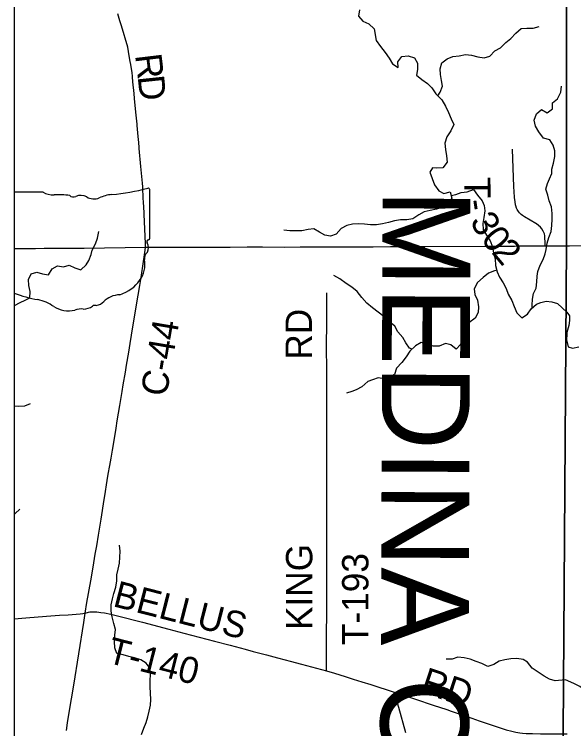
# Model space of a CAD drawing. Extents: x 0 to 34, y 0 to 22.
# Drawn here: x 2.1 to 3.306, y 17.388 to 18.93 of the extents above; entities that cross this region are included whole.
import ezdxf

# ---------------------------------------------------------------- set-up
doc = ezdxf.new("R2010")
doc.units = 0
for name, color, linetype in [('Default', 7, 'Continuous'), ('GM_X_County_Road', 7, 'Continuous'), ('GM_X_County_Road_Text', 7, 'Continuous'), ('GM_X_County_Text', 7, 'Continuous'), ('GM_X_Minor_River', 7, 'Continuous'), ('GM_X_State_Location', 7, 'Continuous'), ('GM_X_State_Route', 7, 'Continuous'), ('GM_X_Township_Road', 7, 'Continuous'), ('GM_X_Township_Road_Text', 7, 'Continuous'), ('SH_Cut_Line', 7, 'Continuous'), ('SH_Data', 7, 'Continuous')]:
    doc.layers.add(name, color=color, linetype=linetype)

msp = doc.modelspace()

# ---------------------------------------------------------------- linework, layer by layer
at = {"layer": 'Default'}
msp.add_lwpolyline([(3.2826, 20.9), (2.1, 20.9), (2.1, 15.8248), (3.2829, 15.8433), (3.2832, 16.3898), (3.2835, 17.0107), (3.2837, 17.3796), (3.2907, 18.4315), (3.2904, 19.1173), (3.2901, 19.68), (3.2888, 19.8918), (3.2845, 20.5998), (3.2843, 20.6124)], close=True, dxfattribs=at)
for points in [[(8.1749, 20.9), (3.2826, 20.9), (3.2843, 20.6124), (3.2845, 20.5998), (3.2888, 19.8918), (3.2901, 19.68), (3.2904, 19.1173), (3.2907, 18.4315), (3.2837, 17.3796), (3.2835, 17.0107), (3.2832, 16.3898), (3.2829, 15.8433), (3.425, 15.8449), (3.4609, 15.8448), (3.6703, 15.8472), (4.3446, 15.8524), (4.6273, 15.8569)], [(2.1621, 18.5464), (2.1, 18.5464), (2.1, 18.3281)], [(2.3919, 18.4467), (2.3919, 18.4467), (2.3919, 18.4467), (2.3919, 18.5516)]]:
    msp.add_lwpolyline(points, dxfattribs=at)
for centre, major_axis, start_param, end_param in [((2.1851, 18.5696), (0.037, 0), 4.042888, 4.731792), ((2.2745, 18.8193), (0.3495, 0), 4.814394, 5.042369), ((2.3883, 18.5518), (0.00367, 0), 6.197627, 7.989034), ((2.1974, 18.4341), (0.133, 0), 1.404758, 1.657859), ((2.2276, 18.5444), (0.0107, 0), 3.836095, 5.185415), ((2.2432, 18.5213), (0.0222, 0), 0.950623, 2.079405), ((2.2719, 18.553), (0.0267, 0), 4.08156, 5.145723), ((2.3191, 18.4853), (0.0703, 0), 1.699012, 2.107814), ((2.3911, 18.439), (0.00568, 0), 1.883978, 3.671073), ((2.355, 18.4258), (0.0341, 0), 5.934695, 6.695948), ((2.388, 18.4463), (0.00393, 0), 5.05454, 6.418171), ((2.4051, 18.4029), (0.0248, 0), 2.387724, 3.262537), ((2.2941, 18.3896), (0.0874, 0), 5.101753, 6.440018), ((2.2066, 18.5111), (0.2524, 0), 4.276441, 4.488961), ((2.1313, 18.2529), (0.079, 0), 0.823519, 1.323587), ((2.331, 18.2867), (0.0479, 0), 1.647645, 2.488434), ((2.2167, 18.3303), (0.0501, 0), 4.026481, 4.996735), ((2.2494, 18.3153), (0.0267, 0), 4.691044, 5.507374), ((2.2735, 18.2959), (0.00752, 0), 1.147584, 2.315152), ((2.2703, 18.3235), (0.0282, 0), 4.937069, 5.64225), ((2.2457, 18.2611), (0.0412, 0), 1.495662, 1.94098)]:
    msp.add_ellipse(centre, major_axis=major_axis, ratio=0.8, start_param=start_param, end_param=end_param, dxfattribs=at)
at = {"layer": 'GM_X_County_Road'}
for points in [[(2.2531, 17.638), (2.2567, 17.6609), (2.2647, 17.7074), (2.2669, 17.7199), (2.2713, 17.7461), (2.2745, 17.765), (2.2776, 17.7829), (2.2815, 17.8061), (2.2871, 17.8402), (2.294, 17.8832), (2.2952, 17.8909), (2.3003, 17.9238), (2.3027, 17.9379), (2.306, 17.9565), (2.3087, 17.9723), (2.3118, 17.9897), (2.3164, 18.0191), (2.3196, 18.037), (2.3221, 18.0527), (2.3278, 18.0857), (2.3325, 18.1159), (2.3349, 18.1303), (2.3397, 18.1578), (2.3421, 18.1731), (2.3468, 18.2012), (2.3499, 18.2198), (2.3559, 18.2555), (2.3669, 18.3236), (2.3705, 18.3444), (2.3727, 18.3575), (2.3772, 18.3867), (2.3823, 18.4206), (2.3829, 18.4275), (2.3832, 18.4351), (2.3808, 18.4822), (2.379, 18.5162), (2.3787, 18.5223), (2.3781, 18.5353), (2.3771, 18.5539), (2.3769, 18.5579), (2.3765, 18.5654), (2.3745, 18.587), (2.3731, 18.6012), (2.3695, 18.6401), (2.3693, 18.6423), (2.3682, 18.6536), (2.3671, 18.6659), (2.3648, 18.6896), (2.3646, 18.6925), (2.3627, 18.712), (2.3614, 18.7258), (2.3593, 18.7483), (2.3583, 18.7588), (2.3559, 18.7845), (2.355, 18.795), (2.3549, 18.7962), (2.3541, 18.8033), (2.3509, 18.8217), (2.3499, 18.8279), (2.3477, 18.8402), (2.3445, 18.8589), (2.3309, 18.9051), (2.3278, 18.9158), (2.3234, 18.9309)], [(2.1, 17.6257), (2.1249, 17.6276), (2.1511, 17.6298), (2.179, 17.6319), (2.1978, 17.6331), (2.2159, 17.6344), (2.2419, 17.6362), (2.2476, 17.6369), (2.2531, 17.638)], [(2.2122, 17.3845), (2.2146, 17.4013), (2.2185, 17.4236), (2.2283, 17.4825), (2.2497, 17.6178), (2.2531, 17.638)]]:
    msp.add_lwpolyline(points, dxfattribs=at)
at = {"layer": 'GM_X_Minor_River'}
for points in [[(2.8439, 18.9397), (2.8424, 18.926), (2.8515, 18.9153), (2.8641, 18.9096), (2.8759, 18.8986), (2.8805, 18.8735), (2.8893, 18.8606), (2.8996, 18.8477), (2.908, 18.8352), (2.9156, 18.823), (2.9274, 18.815), (2.927, 18.8276), (2.9357, 18.839), (2.9494, 18.8405), (2.9631, 18.836), (2.9692, 18.8246), (2.9693, 18.8109), (2.9674, 18.7983), (2.9788, 18.7892), (2.9906, 18.7809), (3.0005, 18.7714), (3.0089, 18.7585), (3.0215, 18.7452), (3.0295, 18.7319), (3.0364, 18.7182), (3.0421, 18.7045), (3.0474, 18.692), (3.0414, 18.6783), (3.0322, 18.6657), (3.0285, 18.652), (3.0296, 18.6383), (3.0319, 18.6246), (3.0335, 18.6109), (3.024, 18.5988), (3.011, 18.5976), (3.0015, 18.5987), (2.9958, 18.5892), (3.0012, 18.5755), (3.0061, 18.5622), (3.0153, 18.5493), (3.0263, 18.5432), (3.0396, 18.5467), (3.0435, 18.533), (3.0355, 18.5204), (3.023, 18.5139), (3.01, 18.5097), (2.9967, 18.5067), (2.9838, 18.504), (2.972, 18.4971), (2.9594, 18.4888), (2.9465, 18.4861), (2.9328, 18.4861), (2.9195, 18.4845), (2.9066, 18.4807), (2.894, 18.478), (2.8807, 18.4753), (2.8678, 18.4757), (2.8548, 18.4768), (2.8423, 18.478), (2.8293, 18.4768), (2.8172, 18.4741), (2.8046, 18.4676), (2.794, 18.4554), (2.7814, 18.4509), (2.7692, 18.4531), (2.7582, 18.46), (2.7456, 18.4672), (2.7335, 18.4656), (2.7201, 18.463), (2.7072, 18.4626), (2.6943, 18.4629), (2.6813, 18.4644)], [(3.0131, 18.7541), (3.018, 18.7619), (3.023, 18.7748), (3.0207, 18.7874), (3.0191, 18.8003), (3.0183, 18.8121), (3.0214, 18.825), (3.0331, 18.8338), (3.0457, 18.8391), (3.0594, 18.8403), (3.0731, 18.843), (3.086, 18.8419), (3.0993, 18.8381), (3.1127, 18.8358), (3.1252, 18.8393), (3.1359, 18.8511), (3.1484, 18.8575), (3.1598, 18.8693), (3.1708, 18.8777), (3.1811, 18.8891), (3.1925, 18.8994), (3.205, 18.9002), (3.2187, 18.8998), (3.2313, 18.9037)], [(3.2164, 18.296), (3.2165, 18.302), (3.2169, 18.3153), (3.2196, 18.3271), (3.2252, 18.3389), (3.2264, 18.3526), (3.2271, 18.3651), (3.2286, 18.375), (3.2335, 18.3883), (3.24, 18.4005), (3.2442, 18.4127), (3.2468, 18.4226), (3.2491, 18.4359), (3.2521, 18.4481), (3.2574, 18.4614), (3.2589, 18.4743), (3.2593, 18.488), (3.2596, 18.5002), (3.2585, 18.5143), (3.2535, 18.5272), (3.2505, 18.5393), (3.2462, 18.5527), (3.2497, 18.5648), (3.2542, 18.5747), (3.2588, 18.5861), (3.2591, 18.5956), (3.2625, 18.6086), (3.2652, 18.6227), (3.2652, 18.6352), (3.2617, 18.6478), (3.2545, 18.6592), (3.2408, 18.6626), (3.2309, 18.6762), (3.2236, 18.6888), (3.2205, 18.7017), (3.2255, 18.715), (3.2369, 18.7242), (3.2487, 18.7173), (3.2601, 18.7261), (3.2604, 18.7386), (3.2711, 18.7478), (3.2783, 18.7619), (3.2798, 18.7748)], [(3.0418, 18.5391), (3.0518, 18.541), (3.0636, 18.5452), (3.0766, 18.5471), (3.0899, 18.5521), (3.0986, 18.5399), (3.1089, 18.5274), (3.1131, 18.5175), (3.1143, 18.5057), (3.112, 18.4912), (3.1098, 18.4783), (3.1109, 18.4654), (3.1182, 18.4532), (3.1258, 18.4411), (3.1311, 18.4285), (3.1334, 18.4148), (3.1369, 18.4019), (3.1377, 18.3882), (3.1407, 18.3745), (3.1461, 18.3624), (3.1541, 18.3506), (3.1606, 18.338), (3.1651, 18.3259), (3.1728, 18.3126), (3.1777, 18.2993), (3.1838, 18.2856), (3.1945, 18.2746), (3.2063, 18.2826), (3.2147, 18.2944), (3.2257, 18.3047), (3.2352, 18.3077), (3.247, 18.3108), (3.2592, 18.3096), (3.2713, 18.3062), (3.2911, 18.2869)], [(2.1, 18.3014), (2.1002, 18.3017), (2.1123, 18.3082), (2.1237, 18.3131), (2.1332, 18.3184), (2.1344, 18.3318), (2.1313, 18.3447), (2.1309, 18.3576), (2.1362, 18.3702), (2.1484, 18.3736), (2.161, 18.3702), (2.1735, 18.3676), (2.1819, 18.3809), (2.1929, 18.387), (2.2058, 18.3847), (2.2184, 18.3889), (2.2302, 18.3828), (2.2435, 18.3787), (2.2553, 18.389), (2.261, 18.3985), (2.2655, 18.4114), (2.2682, 18.4209), (2.275, 18.4346), (2.2792, 18.4472), (2.2822, 18.4613)], [(3.14, 18.3776), (3.135, 18.3764), (3.1225, 18.3715), (3.1107, 18.3619), (3.0989, 18.3509), (3.0913, 18.3376), (3.0932, 18.3254), (3.0986, 18.3129), (3.1009, 18.2988), (3.0998, 18.2866), (3.0933, 18.2744), (3.08, 18.2641), (3.0697, 18.2542), (3.0663, 18.2413), (3.0645, 18.2288), (3.0622, 18.2173), (3.0523, 18.2071), (3.0413, 18.2166), (3.0295, 18.2196), (3.0158, 18.2139), (3.0028, 18.2135), (2.9907, 18.2184), (2.977, 18.2214), (2.9652, 18.2146), (2.953, 18.2027), (2.9447, 18.1906), (2.9355, 18.1784), (2.9241, 18.1662), (2.92, 18.1529), (2.9074, 18.1449), (2.8979, 18.143), (2.8846, 18.1456), (2.8721, 18.141), (2.8625, 18.1376), (2.8496, 18.1262), (2.8371, 18.1193), (2.8276, 18.1162), (2.8162, 18.1124)], [(2.9576, 18.2072), (2.9522, 18.2092), (2.9442, 18.221), (2.9374, 18.2328), (2.9271, 18.2445), (2.9202, 18.2567), (2.9092, 18.2662), (2.897, 18.278), (2.8848, 18.2875), (2.8722, 18.2966), (2.8604, 18.3068), (2.8493, 18.319), (2.8391, 18.3315), (2.8276, 18.3414), (2.8158, 18.349), (2.8021, 18.3589), (2.7892, 18.3661)], [(3.2911, 18.2869), (3.2968, 18.2796), (3.2969, 18.2689), (3.2955, 18.2583), (3.291, 18.2435), (3.291, 18.2389), (3.2907, 18.2278), (3.294, 18.2123), (3.3035, 18.2093), (3.3172, 18.2121)], [(2.1, 18.0848), (2.11, 18.0845), (2.1225, 18.0853), (2.1351, 18.0899)], [(2.1, 17.8522), (2.1016, 17.8529), (2.1122, 17.862)], [(2.3743, 17.376), (2.3793, 17.3896), (2.3846, 17.4018), (2.388, 17.414), (2.3906, 17.4266), (2.3933, 17.4395), (2.3944, 17.4517), (2.394, 17.4653), (2.3932, 17.479), (2.3928, 17.4927), (2.3935, 17.5057), (2.3928, 17.5186), (2.3844, 17.53), (2.3729, 17.5372), (2.3592, 17.541), (2.3467, 17.5444), (2.3345, 17.5478), (2.3212, 17.5508), (2.3166, 17.563), (2.3158, 17.5767), (2.3169, 17.5904), (2.3184, 17.6025), (2.3146, 17.6151), (2.3112, 17.6295), (2.3089, 17.6421), (2.3089, 17.6554), (2.3115, 17.6683), (2.3149, 17.6805), (2.3191, 17.6938), (2.3213, 17.7075), (2.3209, 17.7204), (2.324, 17.7326), (2.327, 17.7456), (2.3277, 17.7585), (2.3281, 17.7714), (2.3269, 17.7843)], [(3.2884, 17.4941), (3.266, 17.4916), (3.2539, 17.4954), (3.2421, 17.5018), (3.2291, 17.5102), (3.2162, 17.5193), (3.2066, 17.5318), (3.1971, 17.5375), (3.1834, 17.5402), (3.1705, 17.539), (3.1575, 17.5371), (3.1454, 17.5344), (3.1336, 17.5272), (3.121, 17.5226), (3.1081, 17.5294), (3.0959, 17.5336), (3.083, 17.5385), (3.07, 17.5415), (3.0563, 17.543), (3.0441, 17.5388), (3.0308, 17.5384)], [(3.408, 17.447), (3.3831, 17.4577), (3.3668, 17.4602), (3.3543, 17.4616), (3.3394, 17.4645), (3.3291, 17.472), (3.3196, 17.4792), (3.3066, 17.4863), (3.2884, 17.4941)]]:
    msp.add_lwpolyline(points, dxfattribs=at)
at = {"layer": 'GM_X_State_Route'}
for points in [[(3.2967, 18.4306), (3.4179, 18.4325), (3.729, 18.4357), (4.1827, 18.4379)], [(2.1, 18.4247), (2.1087, 18.4248), (2.1455, 18.4249), (2.1647, 18.425), (2.1927, 18.4252), (2.2169, 18.4254), (2.2507, 18.4256), (2.3829, 18.4275), (2.4256, 18.4276), (2.502, 18.4277), (2.5452, 18.4276), (2.5656, 18.4277), (2.6022, 18.428), (2.6207, 18.4278), (2.6353, 18.428), (2.6822, 18.4277), (2.7166, 18.4278), (2.773, 18.428), (2.7956, 18.4281), (2.8148, 18.4282), (2.8739, 18.4285), (2.9114, 18.4286), (2.9638, 18.4289), (2.9854, 18.429), (3.1147, 18.4297)], [(3.1147, 18.4297), (3.1458, 18.4298), (3.1785, 18.4299), (3.1845, 18.43)], [(3.1845, 18.43), (3.2445, 18.4301), (3.272, 18.4302), (3.2967, 18.4306)]]:
    msp.add_lwpolyline(points, dxfattribs=at)
at = {"layer": 'GM_X_Township_Road'}
for points in [[(3.2445, 18.4301), (3.2443, 18.4383), (3.2441, 18.4476), (3.2437, 18.4518), (3.2429, 18.4562), (3.2405, 18.4622), (3.2375, 18.4673), (3.2346, 18.4709), (3.2302, 18.4744), (3.2256, 18.4776), (3.2241, 18.4785), (3.1998, 18.4928), (3.1959, 18.4954), (3.1927, 18.4981), (3.189, 18.5017), (3.1869, 18.5043), (3.1843, 18.5084), (3.183, 18.5116), (3.1814, 18.5164), (3.1808, 18.519), (3.1796, 18.5255), (3.1786, 18.5343), (3.1778, 18.5474), (3.1772, 18.5577), (3.1739, 18.6391)], [(2.773, 17.513), (2.7732, 17.6024), (2.7735, 17.6273), (2.7737, 17.6563), (2.7738, 17.6859), (2.774, 17.7444), (2.7737, 17.7733), (2.7735, 17.8034), (2.7738, 17.8316), (2.7737, 18.1519), (2.7733, 18.2224), (2.7735, 18.256), (2.7735, 18.3287)], [(2.2531, 17.638), (2.2603, 17.6398), (2.263, 17.6405), (2.2661, 17.6408), (2.2706, 17.6409), (2.2776, 17.6403), (2.2863, 17.6393), (2.2944, 17.6382), (2.3081, 17.6354), (2.3223, 17.632), (2.3767, 17.618), (2.433, 17.6032), (2.4658, 17.5946), (2.4986, 17.5859), (2.5318, 17.5773), (2.5651, 17.5687), (2.5974, 17.56), (2.6153, 17.5551), (2.6438, 17.5477), (2.6678, 17.5413), (2.6837, 17.5371), (2.6947, 17.5343), (2.7194, 17.5278), (2.773, 17.513), (2.7904, 17.5079), (2.813, 17.501), (2.8304, 17.4956), (2.8492, 17.4898), (2.8684, 17.4836), (2.9191, 17.4674)], [(2.9443, 17.3794), (2.9288, 17.4341), (2.9191, 17.4674)], [(2.9191, 17.4674), (2.9653, 17.4521), (3.0033, 17.4395), (3.0322, 17.4297), (3.0417, 17.4264), (3.0867, 17.4111), (3.1023, 17.4056), (3.1559, 17.3877), (3.1607, 17.3862), (3.1724, 17.3831), (3.1812, 17.381), (3.1853, 17.3802), (3.1897, 17.3797), (3.1958, 17.379), (3.2037, 17.3784), (3.2172, 17.3778), (3.2342, 17.3775), (3.2489, 17.3774), (3.292, 17.3777)]]:
    msp.add_lwpolyline(points, dxfattribs=at)
at = {"layer": 'SH_Cut_Line'}
for points in [[(3.2826, 20.9), (2.1, 20.9), (2.1, 14.1), (3.2807, 14.1), (3.2808, 14.1155), (3.2822, 14.2781), (3.2841, 14.501), (3.2832, 14.8896), (3.2811, 15.7294), (3.2815, 15.7537), (3.2829, 15.8433), (3.2832, 16.3898), (3.2835, 17.0107), (3.2837, 17.3796), (3.2907, 18.4315), (3.2904, 19.1173), (3.2901, 19.68), (3.2888, 19.8918), (3.2845, 20.5998), (3.2843, 20.6124)], [(3.2807, 14.1), (8.9, 14.1), (8.9, 20.9), (3.2826, 20.9), (3.2843, 20.6124), (3.2845, 20.5998), (3.2888, 19.8918), (3.2901, 19.68), (3.2904, 19.1173), (3.2907, 18.4315), (3.2837, 17.3796), (3.2835, 17.0107), (3.2832, 16.3898), (3.2829, 15.8433), (3.2815, 15.7537), (3.2811, 15.7294), (3.2832, 14.8896), (3.2841, 14.501), (3.2822, 14.2781), (3.2808, 14.1155)]]:
    msp.add_lwpolyline(points, close=True, dxfattribs=at)
at = {"layer": 'SH_Data'}
msp.add_line((2.1, 20.9), (2.1, 14.1), dxfattribs=at)

# ---------------------------------------------------------------- texts
at = {"layer": 'GM_X_County_Road_Text'}
for s, height, rotation, p in [('R', 0.0568, 276.8975, (2.3603, 18.8418)), ('D', 0.0568, 275.9741, (2.3659, 18.7957)), ('C-44', 0.05682, 80.3689, (2.4281, 18.1032))]:
    msp.add_text(s, height=height, rotation=rotation, dxfattribs=at).set_placement(p)
at = {"layer": 'GM_X_County_Text'}
msp.add_text('MEDINA COUNTY', height=0.189394, rotation=269.7794, dxfattribs=at).set_placement((2.8942, 18.553))
at = {"layer": 'GM_X_State_Location'}
for s in ['s', 'r']:
    msp.add_text(s, height=0.000189, dxfattribs=at).set_placement((2.2234, 18.4296))
msp.add_text('303', height=0.000189, rotation=0, dxfattribs=at).set_placement((2.1566, 18.4158))
at = {"layer": 'GM_X_Township_Road_Text'}
for s, height, rotation, p in [('T', 0.0568, 270.6128, (3.0697, 18.5787)), ('-', 0.0568, 278.4303, (3.0708, 18.5278)), ('3', 0.0568, 299.0921, (3.0814, 18.4837)), ('0', 0.0568, 308.8103, (3.1042, 18.4444)), ('2', 0.0568, 310.1014, (3.1271, 18.4161)), ('RD', 0.05682, 90, (2.7417, 18.1847)), ('KING', 0.05682, 90, (2.7426, 17.6014)), ('T-193', 0.05682, 90, (2.8635, 17.5689)), ('BELLUS', 0.05682, 345.6552, (2.3104, 17.6531)), ('T-140', 0.05682, 345.6951, (2.2973, 17.5316)), ('RD', 0.05682, 341.8786, (2.9727, 17.4676))]:
    msp.add_text(s, height=height, rotation=rotation, dxfattribs=at).set_placement(p)

doc.saveas('drawing.dxf')
